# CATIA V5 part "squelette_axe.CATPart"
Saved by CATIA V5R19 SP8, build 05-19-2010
Part number: squelette_axe
Publications: "Droite.1"
Bounding box of the stored display mesh (mm): x 83 to 83, y 30.629 to 30.629, z 64.516 to 64.516
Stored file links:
  G:\EU_thinkMotion\CFAO_2010\MMS_groupe3\MMS_groupe3\A reprendre\amenand\amenand\squelette_axe.CATPart
  F:\thinkmotion CFAO v12.1\essuie_glace.CATProduct
  G:\EU_thinkMotion\CFAO_2010\MMS_groupe3\MMS_groupe3\A reprendre\amenand\amenand\bielle.CATPart
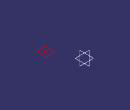
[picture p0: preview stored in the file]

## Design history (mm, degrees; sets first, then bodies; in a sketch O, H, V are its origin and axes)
Set1
  Point1: linked copy from another document
  Plane1: linked copy from another document
Body1 (main body)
